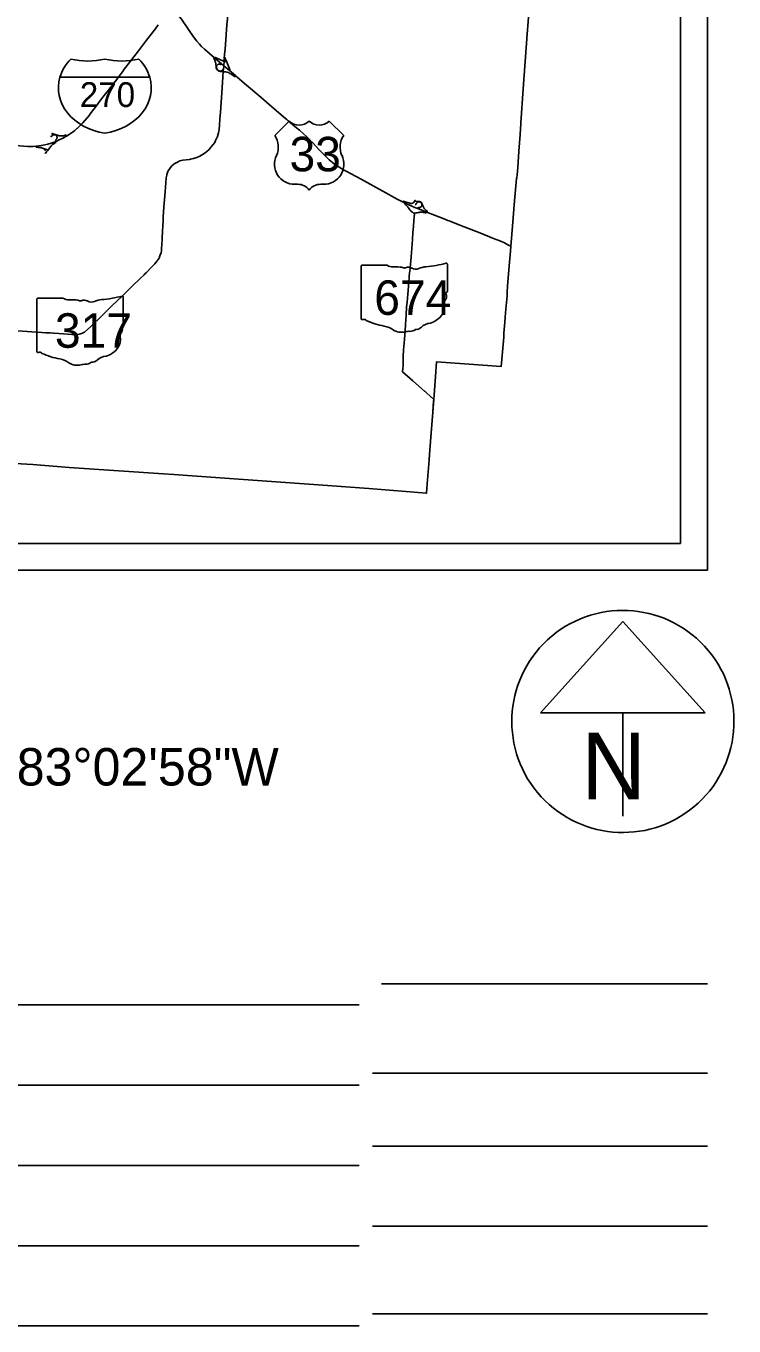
# Model space of a CAD drawing. Extents: x -7.1 to 34, y 0 to 22.
# Drawn here: x 6.456 to 9.099, y 11.177 to 16.034 of the extents above; entities that cross this region are included whole.
import ezdxf

# ---------------------------------------------------------------- set-up
doc = ezdxf.new("R2010")
doc.units = 0
for name, color, linetype in [('GM_X_County', 7, 'Continuous'), ('GM_X_Interchange_Ramps', 7, 'Continuous'), ('GM_X_Interstate_Route', 7, 'Continuous'), ('GM_X_Interstate_Shield', 7, 'Continuous'), ('GM_X_State_Route', 7, 'Continuous'), ('GM_X_State_Shield', 7, 'Continuous'), ('GM_X_US_Route', 7, 'Continuous'), ('GM_X_US_Shield', 7, 'Continuous'), ('SH_Data', 7, 'Continuous'), ('SH_Text', 7, 'Continuous')]:
    doc.layers.add(name, color=color, linetype=linetype)

msp = doc.modelspace()

# ---------------------------------------------------------------- linework, layer by layer
at = {"layer": 'GM_X_County'}
msp.add_lwpolyline([(8.3452, 16.241), (8.3276, 16.0031), (8.3124, 15.7982), (8.3039, 15.672), (8.304, 15.6696), (8.3007, 15.6277), (8.2962, 15.5663), (8.2918, 15.5054), (8.2895, 15.4769), (8.2885, 15.4678), (8.2869, 15.4635), (8.2799, 15.3798), (8.2697, 15.255), (8.2659, 15.2104), (8.2648, 15.1927), (8.2633, 15.1786), (8.262, 15.1645), (8.2613, 15.1511), (8.2536, 15.0634), (8.2526, 15.0382), (8.2529, 15.0363), (8.2526, 15.0324), (8.2521, 15.0258), (8.2478, 14.9762), (8.2466, 14.9608), (8.2454, 14.9453), (8.2439, 14.9276), (8.2404, 14.8854), (8.2396, 14.8706), (8.2296, 14.7611), (8.111, 14.7704), (7.9888, 14.7793), (7.9845, 14.7241), (7.9794, 14.6555), (7.9781, 14.638), (7.9638, 14.4503), (7.9612, 14.4126), (7.9539, 14.3229), (7.9514, 14.288), (7.7354, 14.3054), (7.582, 14.317), (7.338, 14.3346), (7.2153, 14.3436), (7.0933, 14.3519), (7.0075, 14.3585), (6.9696, 14.3609), (6.617, 14.3844), (6.4816, 14.3958), (6.2397, 14.409)], dxfattribs=at)
at = {"layer": 'GM_X_Interchange_Ramps'}
for points in [[(7.1594, 15.9152), (7.1567, 15.9122), (7.1586, 15.9096), (7.1597, 15.9078), (7.1607, 15.9059), (7.1614, 15.9043), (7.1621, 15.9026), (7.1628, 15.9008), (7.1633, 15.8989), (7.1638, 15.8965), (7.1641, 15.8941), (7.1658, 15.8772), (7.1664, 15.875), (7.1671, 15.8733), (7.1679, 15.8718), (7.1691, 15.8702), (7.1706, 15.8686), (7.1718, 15.8675), (7.1733, 15.8665), (7.1748, 15.8657), (7.1761, 15.8651), (7.1779, 15.8646), (7.1795, 15.8643), (7.1817, 15.864), (7.1905, 15.8631), (7.1924, 15.863)], [(7.1952, 15.9017), (7.1938, 15.9018), (7.1687, 15.9134), (7.1636, 15.9163), (7.1612, 15.9136)], [(7.193, 15.8705), (7.1905, 15.8707), (7.1896, 15.8695), (7.1884, 15.8683), (7.1872, 15.8673), (7.1859, 15.8666), (7.1847, 15.8661), (7.1835, 15.8657), (7.1818, 15.8654), (7.1802, 15.8654), (7.1786, 15.8656), (7.1769, 15.8661), (7.1742, 15.8675), (7.1723, 15.8688), (7.1707, 15.8703), (7.1693, 15.8721), (7.1684, 15.8737), (7.1678, 15.8751), (7.1672, 15.8771), (7.1669, 15.8791), (7.1669, 15.8813), (7.1673, 15.8835), (7.1679, 15.8849), (7.1685, 15.8862), (7.1694, 15.8873), (7.1708, 15.8887), (7.1722, 15.8896), (7.1738, 15.8904), (7.1754, 15.8909), (7.177, 15.8911), (7.1788, 15.891), (7.1802, 15.8908), (7.1814, 15.8904), (7.183, 15.8897), (7.1858, 15.8925)], [(7.2053, 15.8984), (7.2047, 15.8982), (7.2039, 15.8991), (7.2028, 15.9), (7.2017, 15.9006), (7.2004, 15.9012), (7.1991, 15.9015), (7.1983, 15.9015), (7.1974, 15.9016), (7.1952, 15.9017)], [(7.2152, 15.8674), (7.2175, 15.8699), (7.2155, 15.8736), (7.2053, 15.8984), (7.1995, 15.9125), (7.1984, 15.9154), (7.1961, 15.9155)], [(7.1924, 15.863), (7.194, 15.8629), (7.1986, 15.8625), (7.2001, 15.8624), (7.2019, 15.8621), (7.2068, 15.861), (7.2107, 15.8598), (7.2142, 15.8582), (7.2173, 15.8566), (7.2204, 15.8547), (7.2364, 15.8441), (7.239, 15.847)], [(6.5266, 15.5596), (6.5297, 15.5585), (6.5311, 15.5607), (6.5328, 15.5633), (6.536, 15.5674), (6.5398, 15.5718), (6.5471, 15.5826), (6.5482, 15.5838), (6.5496, 15.5853), (6.551, 15.5867), (6.5524, 15.588), (6.554, 15.5894), (6.5554, 15.5906), (6.5568, 15.5916), (6.5585, 15.5929), (6.5618, 15.595), (6.5631, 15.5958), (6.5648, 15.5968), (6.5667, 15.5977), (6.5653, 15.6013)], [(6.5479, 15.6216), (6.551, 15.6205), (6.5524, 15.6224), (6.5537, 15.624), (6.5549, 15.625), (6.5561, 15.6257), (6.5582, 15.6268), (6.5602, 15.6272), (6.562, 15.6273), (6.5643, 15.627), (6.5657, 15.6265), (6.5679, 15.6254), (6.5692, 15.6241), (6.5702, 15.6228), (6.5709, 15.6216), (6.5714, 15.6202), (6.5718, 15.6184), (6.5719, 15.6165), (6.5716, 15.6144), (6.571, 15.6126), (6.5703, 15.6111), (6.5689, 15.6095), (6.5677, 15.6084), (6.5664, 15.6075), (6.5683, 15.6025)], [(6.5515, 15.6315), (6.5531, 15.631), (6.5602, 15.6287), (6.5602, 15.6272)], [(6.607, 15.6222), (6.6042, 15.6264), (6.6024, 15.6256), (6.6006, 15.6248), (6.5986, 15.6241), (6.5967, 15.6236), (6.5947, 15.6232), (6.5931, 15.6229), (6.5909, 15.6227), (6.5887, 15.6226), (6.5864, 15.6226), (6.584, 15.6228), (6.5817, 15.6232), (6.5794, 15.6237), (6.5766, 15.6246), (6.5642, 15.6286), (6.5534, 15.6321), (6.5519, 15.6326)], [(6.4939, 15.5841), (6.4942, 15.5806), (6.5013, 15.5802), (6.503, 15.5802), (6.5049, 15.58), (6.5066, 15.5798), (6.5081, 15.5795), (6.5098, 15.5792), (6.5112, 15.5789), (6.5129, 15.5785), (6.5152, 15.5778), (6.5172, 15.5772), (6.5191, 15.5765), (6.5217, 15.5753), (6.5226, 15.5748), (6.5235, 15.5742), (6.5242, 15.5736), (6.5247, 15.573), (6.5253, 15.5722), (6.5258, 15.5712), (6.5263, 15.5702), (6.5297, 15.5688)], [(6.5217, 15.5753), (6.5218, 15.5756), (6.5281, 15.5735), (6.5309, 15.5721)], [(6.5309, 15.5721), (6.5326, 15.5716), (6.5343, 15.5712), (6.5355, 15.5711), (6.5368, 15.5713), (6.5381, 15.5717), (6.5393, 15.5724), (6.5398, 15.5718)], [(7.91, 15.3812), (7.9072, 15.3814), (7.9062, 15.3787), (7.9055, 15.3772), (7.9046, 15.3759), (7.9036, 15.3747), (7.9024, 15.3735), (7.9012, 15.3727), (7.8997, 15.3719), (7.898, 15.3713), (7.8965, 15.3709), (7.8952, 15.3708), (7.8937, 15.3707), (7.892, 15.3709), (7.8865, 15.3723), (7.8715, 15.377), (7.8655, 15.3792), (7.8637, 15.3754)], [(7.8722, 15.3713), (7.8707, 15.368), (7.872, 15.367), (7.8739, 15.3654), (7.8757, 15.3637), (7.8779, 15.3616), (7.88, 15.3592), (7.8819, 15.357), (7.8836, 15.3546), (7.8889, 15.347), (7.89, 15.3454), (7.8914, 15.3437), (7.8929, 15.3421), (7.8947, 15.3405), (7.8968, 15.339), (7.8986, 15.3376), (7.9003, 15.3365), (7.9018, 15.3357), (7.9032, 15.3349), (7.9063, 15.3342)], [(7.9089, 15.3664), (7.9109, 15.3662), (7.9117, 15.3683), (7.9124, 15.3696), (7.9134, 15.3714), (7.9146, 15.3729), (7.9157, 15.3741), (7.9174, 15.3753), (7.9193, 15.3762), (7.9214, 15.3768), (7.9236, 15.3769), (7.9256, 15.3766), (7.9273, 15.376), (7.9289, 15.3752), (7.9301, 15.3743), (7.9314, 15.3731), (7.9323, 15.3718), (7.933, 15.3705), (7.9337, 15.3688), (7.934, 15.367), (7.934, 15.3653), (7.9338, 15.3636), (7.9334, 15.362), (7.9327, 15.3606), (7.9318, 15.3593), (7.9308, 15.358), (7.9294, 15.3569), (7.9278, 15.356), (7.9262, 15.3553), (7.9246, 15.355), (7.9221, 15.3549), (7.9209, 15.3552), (7.9192, 15.3513)], [(7.9525, 15.3381), (7.9542, 15.3419), (7.9521, 15.3432), (7.9503, 15.3444), (7.9487, 15.3456), (7.9473, 15.3469), (7.9457, 15.3484), (7.9442, 15.3502), (7.9431, 15.3515), (7.9421, 15.353), (7.9411, 15.3545), (7.9401, 15.3563), (7.9394, 15.3579), (7.9388, 15.3593), (7.9343, 15.3704), (7.9334, 15.3722), (7.9322, 15.3738), (7.931, 15.375), (7.9295, 15.3761), (7.9282, 15.3768), (7.9269, 15.3774), (7.9251, 15.3778), (7.9226, 15.3784), (7.911, 15.379), (7.9098, 15.3791)]]:
    msp.add_lwpolyline(points, dxfattribs=at)
at = {"layer": 'GM_X_Interstate_Route'}
for points in [[(6.9491, 16.0374), (6.938, 16.0223), (6.9058, 15.9807), (6.88, 15.9462), (6.8459, 15.9025), (6.8229, 15.8718)], [(6.8157, 15.8622), (6.8112, 15.8562), (6.7971, 15.8373), (6.7622, 15.7924), (6.7383, 15.7616), (6.7143, 15.7292), (6.7102, 15.7237), (6.7093, 15.7225)], [(6.8229, 15.8718), (6.8158, 15.8623), (6.8157, 15.8622)], [(6.6947, 15.7033), (6.6928, 15.7008), (6.668, 15.6718), (6.6546, 15.6581), (6.6466, 15.6505), (6.6461, 15.6501)], [(6.7093, 15.7225), (6.6958, 15.7048), (6.6947, 15.7033)], [(6.6461, 15.6501), (6.6382, 15.6432), (6.6288, 15.6362), (6.607, 15.6222), (6.5933, 15.6141), (6.5776, 15.6067), (6.5683, 15.6025), (6.5653, 15.6013), (6.5622, 15.6), (6.5612, 15.5996)], [(6.5376, 15.5925), (6.526, 15.5895), (6.513, 15.5868), (6.4939, 15.5841), (6.4831, 15.5835), (6.4614, 15.5831), (6.4322, 15.5853), (6.3196, 15.593), (6.3129, 15.5934), (6.3105, 15.5936)], [(6.5612, 15.5996), (6.5608, 15.5994), (6.5499, 15.5956), (6.5376, 15.5925)]]:
    msp.add_lwpolyline(points, dxfattribs=at)
at = {"layer": 'GM_X_Interstate_Shield'}
msp.add_line((6.918, 15.8422), (6.5824, 15.8422), dxfattribs=at)
msp.add_line((6.918, 15.8422), (6.5824, 15.8422), dxfattribs=at)
for centre, start_param, end_param in [((6.7936, 15.8026), 2.47259, 2.911027), ((6.6868, 16.0762), 4.415841, 5.008937), ((6.8136, 16.0762), 4.415841, 5.008937), ((6.7069, 15.8026), 0.230566, 0.669003), ((6.7936, 15.8026), 2.911027, 4.511031), ((6.7069, 15.8026), 4.913747, 6.513751)]:
    msp.add_ellipse(centre, major_axis=(0.2169, 0), ratio=0.8, start_param=start_param, end_param=end_param, dxfattribs=at)
at = {"layer": 'GM_X_State_Route'}
for points in [[(7.1972, 15.928), (7.1989, 15.9466), (7.2059, 16.0375), (7.2079, 16.0605), (7.2092, 16.0799)], [(7.1926, 15.8655), (7.193, 15.8705), (7.1941, 15.8853)], [(7.1941, 15.8853), (7.1952, 15.9017), (7.1961, 15.9155), (7.1967, 15.923)], [(7.1967, 15.923), (7.1972, 15.928)], [(6.9819, 15.479), (6.9839, 15.4857), (6.9872, 15.4927), (6.9926, 15.5013), (6.9995, 15.5098), (7.0091, 15.5181), (7.0141, 15.5214), (7.0212, 15.5254), (7.0303, 15.5293), (7.0354, 15.531), (7.0409, 15.5322), (7.0658, 15.5351), (7.0745, 15.5367), (7.0812, 15.5382), (7.0936, 15.5423), (7.1044, 15.5471), (7.1148, 15.5529), (7.1245, 15.5596), (7.1311, 15.5646), (7.1397, 15.5727), (7.1466, 15.5807), (7.1543, 15.5903), (7.1606, 15.5989), (7.164, 15.6055), (7.1676, 15.6132), (7.1708, 15.621), (7.1746, 15.6347), (7.176, 15.6411), (7.1766, 15.6476), (7.1781, 15.6622), (7.1801, 15.6872), (7.1816, 15.7098), (7.1849, 15.7496), (7.1873, 15.7823), (7.1911, 15.844)], [(7.1911, 15.844), (7.1924, 15.863), (7.1926, 15.8655)], [(6.9686, 15.32), (6.9711, 15.3569), (6.975, 15.4138), (6.979, 15.4657), (6.9812, 15.4766), (6.9819, 15.479)], [(6.9668, 15.2835), (6.9671, 15.2885), (6.9676, 15.3045), (6.9686, 15.32)], [(7.8987, 15.2375), (7.9007, 15.2617), (7.9025, 15.2842), (7.9044, 15.3087), (7.9051, 15.3176)], [(7.9051, 15.3176), (7.9063, 15.3342)], [(7.9063, 15.3342), (7.9112, 15.335), (7.9164, 15.3359), (7.921, 15.3368), (7.9237, 15.3371), (7.926, 15.3375), (7.9291, 15.3376), (7.9327, 15.3377), (7.9364, 15.3375), (7.9396, 15.3373), (7.9433, 15.3367), (7.9465, 15.3361), (7.9492, 15.3361), (7.9548, 15.3371)], [(6.9052, 15.113), (6.9231, 15.1311), (6.9367, 15.1451), (6.9461, 15.156), (6.9525, 15.1664), (6.9558, 15.1747), (6.96, 15.1868), (6.9612, 15.192), (6.9624, 15.2014), (6.9646, 15.2356), (6.966, 15.2715), (6.9667, 15.2824), (6.9668, 15.2835)], [(7.8915, 15.1465), (7.8924, 15.1539), (7.8937, 15.1726), (7.8947, 15.1846), (7.896, 15.2046), (7.8984, 15.2345), (7.8987, 15.2375)], [(6.8965, 15.1043), (6.9001, 15.1079), (6.9052, 15.113)], [(7.8638, 14.7871), (7.8637, 14.7891), (7.8637, 14.7977), (7.8638, 14.8018), (7.864, 14.805), (7.8642, 14.8088), (7.8648, 14.8152), (7.8657, 14.824), (7.8676, 14.8482), (7.8686, 14.8632), (7.871, 14.8943), (7.8725, 14.9186), (7.8748, 14.9534), (7.8771, 14.9839), (7.8787, 15.0019), (7.881, 15.0312), (7.8822, 15.045), (7.8838, 15.0626), (7.8866, 15.093), (7.887, 15.0988), (7.889, 15.1198)], [(7.889, 15.1198), (7.8897, 15.1271), (7.8915, 15.1465)], [(6.6297, 14.8808), (6.6427, 14.8804), (6.6488, 14.881), (6.6545, 14.882), (6.6591, 14.8832), (6.6637, 14.8847), (6.6692, 14.8871), (6.6745, 14.8899), (6.6984, 14.9105), (6.7384, 14.9501), (6.7769, 14.9884), (6.8145, 15.0246), (6.8307, 15.0398), (6.8515, 15.0601), (6.8838, 15.0918), (6.8965, 15.1043)], [(6.3981, 14.8966), (6.4254, 14.895), (6.4778, 14.8913), (6.478, 14.8913)], [(6.478, 14.8913), (6.5149, 14.8884), (6.5289, 14.8874), (6.5315, 14.8873)], [(6.5315, 14.8873), (6.5458, 14.8867), (6.5586, 14.8857), (6.5599, 14.8856)], [(6.5599, 14.8856), (6.5963, 14.8832), (6.6274, 14.8808), (6.6297, 14.8808)], [(7.8633, 14.7554), (7.8633, 14.7556), (7.8637, 14.7623), (7.864, 14.7692), (7.8641, 14.7748), (7.8638, 14.7871)], [(7.8619, 14.7409), (7.8619, 14.7409), (7.8633, 14.7554)], [(7.9781, 14.638), (7.9632, 14.6524), (7.9528, 14.6619), (7.9445, 14.6689), (7.9439, 14.6695), (7.9002, 14.7073), (7.8619, 14.7409)], [(7.9746, 14.5911), (7.9777, 14.6331)], [(7.9777, 14.6331), (7.9781, 14.638)], [(7.9613, 14.4139), (7.9638, 14.4503), (7.9746, 14.5911)]]:
    msp.add_lwpolyline(points, dxfattribs=at)
at = {"layer": 'GM_X_State_Shield'}
for p, q in [((7.7071, 15.1361), (7.7071, 14.9405)), ((7.8046, 15.1395), (7.7103, 15.1395)), ((8.0292, 15.042), (8.0292, 15.1443)), ((6.4964, 15.0132), (6.4964, 14.8176)), ((6.5939, 15.0165), (6.4996, 15.0165)), ((6.8185, 14.9191), (6.8185, 15.0214)), ((8.0292, 15.0421), (8.0292, 15.042)), ((6.8185, 14.9191), (6.8185, 14.9191))]:
    msp.add_line(p, q, dxfattribs=at)
for centre, major_axis, start_param, end_param in [((7.7108, 15.1365), (0.00373, 0), 1.712693, 3.28349), ((7.8271, 15.1622), (0.0362, 0), 4.042523, 4.731795), ((7.8391, 15.0297), (0.1299, 0), 1.404758, 1.657858), ((7.8686, 15.1376), (0.0104, 0), 3.836095, 5.185415), ((7.8839, 15.115), (0.0217, 0), 0.950623, 2.079405), ((7.9119, 15.146), (0.0261, 0), 4.081561, 5.145723), ((7.958, 15.0798), (0.0687, 0), 1.699011, 2.107814), ((7.9145, 15.4061), (0.3416, 0), 4.814394, 5.042369), ((8.0256, 15.1448), (0.00359, 0), 6.141152, 7.989035), ((6.5001, 15.0136), (0.00373, 0), 1.712693, 3.28349), ((6.6164, 15.0392), (0.0362, 0), 4.042523, 4.731795), ((6.6284, 14.9067), (0.1299, 0), 1.404758, 1.657858), ((6.6579, 15.0146), (0.0104, 0), 3.836095, 5.185415), ((6.6732, 14.992), (0.0217, 0), 0.950623, 2.079405), ((6.7473, 14.9568), (0.0687, 0), 1.699011, 2.107814), ((6.7038, 15.2832), (0.3416, 0), 4.814394, 5.042369), ((6.8149, 15.0218), (0.00359, 0), 6.141152, 7.989035), ((8.042, 14.9992), (0.0242, 0), 2.387724, 3.262537), ((8.0284, 15.0345), (0.00555, 0), 1.883978, 3.671073), ((7.9931, 15.0216), (0.0333, 0), 5.934695, 6.695948), ((8.0254, 15.0416), (0.00384, 0), 5.05454, 6.418171), ((6.7012, 15.023), (0.0261, 0), 4.081561, 5.145723), ((7.9336, 14.9862), (0.0854, 0), 5.101752, 6.440018), ((6.8177, 14.9115), (0.00555, 0), 1.883978, 3.671073), ((6.8147, 14.9187), (0.00384, 0), 5.05454, 6.418171), ((7.7108, 14.9401), (0.00376, 0), 3.00124, 4.508301), ((7.7114, 14.9601), (0.0287, 0), 4.665946, 4.897461), ((7.7173, 14.9293), (0.0104, 0), 0.519207, 1.627899), ((7.8481, 15.105), (0.2467, 0), 4.195997, 4.488961), ((7.7745, 14.8527), (0.0772, 0), 0.823519, 1.323587), ((7.9696, 14.8856), (0.0468, 0), 1.647645, 2.488434), ((6.7229, 14.8632), (0.0854, 0), 5.101752, 6.440018), ((6.8314, 14.8762), (0.0242, 0), 2.387724, 3.262537), ((6.7824, 14.8986), (0.0333, 0), 5.934695, 6.695948), ((7.858, 14.9283), (0.049, 0), 4.026481, 4.996735), ((7.8863, 14.8607), (0.0402, 0), 1.495662, 1.94098), ((7.8899, 14.9136), (0.0261, 0), 4.691044, 5.507374), ((7.9135, 14.8947), (0.00735, 0), 1.147584, 2.315152), ((7.9103, 14.9216), (0.0276, 0), 4.937069, 5.64225), ((6.5001, 14.8171), (0.00376, 0), 3.00124, 4.508301), ((6.5007, 14.8372), (0.0287, 0), 4.665946, 4.897461), ((6.5066, 14.8063), (0.0104, 0), 0.519207, 1.627899), ((6.6374, 14.982), (0.2467, 0), 4.195997, 4.488961), ((6.5638, 14.7297), (0.0772, 0), 0.823519, 1.323587), ((6.6473, 14.8053), (0.049, 0), 4.026481, 4.996735), ((6.6756, 14.7377), (0.0402, 0), 1.495662, 1.94098), ((6.6792, 14.7907), (0.0261, 0), 4.691044, 5.507374), ((6.7028, 14.7717), (0.00735, 0), 1.147584, 2.315152), ((6.6996, 14.7986), (0.0276, 0), 4.937069, 5.64225), ((6.7589, 14.7627), (0.0468, 0), 1.647645, 2.488434)]:
    msp.add_ellipse(centre, major_axis=major_axis, ratio=0.8, start_param=start_param, end_param=end_param, dxfattribs=at)
at = {"layer": 'GM_X_US_Route'}
for points in [[(6.9922, 16.1014), (6.9961, 16.0989), (6.998, 16.0975), (7.0035, 16.093), (7.0112, 16.0866), (7.0176, 16.0805), (7.0234, 16.0744), (7.0294, 16.0679), (7.036, 16.0592), (7.0412, 16.0522), (7.055, 16.0319), (7.0705, 16.009), (7.0852, 15.9878), (7.0942, 15.9766), (7.1036, 15.9656), (7.1117, 15.957), (7.122, 15.9472), (7.1594, 15.9152), (7.1612, 15.9136), (7.1858, 15.8925), (7.1941, 15.8853)], [(7.1941, 15.8853), (7.2152, 15.8674), (7.2215, 15.8619)], [(7.2215, 15.8619), (7.239, 15.847), (7.2427, 15.8438)], [(7.2427, 15.8438), (7.2718, 15.8191), (7.2938, 15.8001), (7.3099, 15.7864)], [(7.3099, 15.7864), (7.3338, 15.7659), (7.382, 15.7247), (7.4246, 15.6881), (7.4294, 15.6838), (7.4345, 15.6794), (7.4602, 15.6579), (7.4767, 15.6438), (7.5041, 15.6194), (7.5161, 15.6074), (7.5268, 15.5967), (7.551, 15.5712), (7.5715, 15.5494), (7.5881, 15.5334), (7.6, 15.5236), (7.6094, 15.5165), (7.6199, 15.5093), (7.6323, 15.5017), (7.7068, 15.461), (7.7858, 15.4176), (7.7882, 15.4163)], [(7.7882, 15.4163), (7.8417, 15.387), (7.8637, 15.3754), (7.8722, 15.3713), (7.8849, 15.3654), (7.9082, 15.3557)], [(7.9082, 15.3557), (7.9119, 15.3542)], [(7.9119, 15.3542), (7.9192, 15.3513), (7.9525, 15.3381), (7.9548, 15.3371)], [(7.9548, 15.3371), (7.9815, 15.3268), (8.0136, 15.3141), (8.0307, 15.3074), (8.0308, 15.3074)], [(8.0308, 15.3074), (8.0354, 15.3056)], [(8.0354, 15.3056), (8.0421, 15.303), (8.076, 15.2894), (8.1503, 15.2603), (8.201, 15.2402), (8.2148, 15.2348), (8.2317, 15.2282), (8.2423, 15.2233), (8.258, 15.2151), (8.2659, 15.2104)]]:
    msp.add_lwpolyline(points, dxfattribs=at)
at = {"layer": 'GM_X_US_Shield'}
for p, q in [((7.4381, 15.6785), (7.3844, 15.6248)), ((7.6421, 15.6248), (7.5884, 15.6785)), ((7.4595, 15.4423), (7.4703, 15.4423)), ((7.5562, 15.4423), (7.5669, 15.4423))]:
    msp.add_line(p, q, dxfattribs=at)
for centre, radius, start, end in [((7.4756, 15.7168), 0.0537, 225.573, 314.427), ((7.5508, 15.7168), 0.0537, 225.573, 314.427), ((7.3228, 15.5817), 0.0752, 334.5471, 35.0009), ((7.7036, 15.5817), 0.0752, 144.9991, 205.4529), ((7.4587, 15.5174), 0.0752, 154.8319, 270.6383), ((7.5678, 15.5174), 0.0752, 269.3617, 25.1681), ((7.4703, 15.3886), 0.0537, 36.8699, 90), ((7.5562, 15.3886), 0.0537, 90, 143.1301)]:
    msp.add_arc(centre, radius, start, end, dxfattribs=at)
at = {"layer": 'SH_Data'}
for p, q in [((9, 21), (9, 14)), ((8.9, 20.9), (8.9, 14.1)), ((2.1, 14.1), (8.9, 14.1)), ((2, 14), (9, 14)), ((8.6845, 13.8091), (8.3769, 13.4678)), ((8.9921, 13.4678), (8.6845, 13.8091)), ((8.3769, 13.4678), (8.9921, 13.4678)), ((8.6845, 13.4678), (8.6845, 13.0811)), ((8.6845, 13.4353), (8.6845, 13.4353)), ((8.6845, 13.4353), (8.6845, 13.4353)), ((7.7827, 12.4553), (9, 12.4553)), ((7.7, 12.3767), (4.4937, 12.3767)), ((9, 12.1207), (7.75, 12.1207)), ((7.7, 12.0767), (3.9895, 12.0767)), ((9, 11.8491), (7.75, 11.8491)), ((7.7, 11.7767), (3.6192, 11.7767)), ((9, 11.5491), (7.75, 11.5491)), ((7.7, 11.4767), (3.3288, 11.4767)), ((9, 11.2223), (7.75, 11.2223)), ((7.7, 11.1767), (4.7452, 11.1767))]:
    msp.add_line(p, q, dxfattribs=at)
msp.add_arc((8.6845, 13.4353), 0.4148, 129.7798, 129.7633, dxfattribs=at)

# ---------------------------------------------------------------- texts
at = {"layer": 'GM_X_Interstate_Shield'}
msp.add_text('270', height=0.09255, dxfattribs=at).set_placement((6.6568, 15.7309))
at = {"layer": 'GM_X_State_Shield'}
for s, p in [('674', (7.7563, 14.9543)), ('317', (6.5639, 14.8314))]:
    msp.add_text(s, height=0.12885, dxfattribs=at).set_placement(p)
at = {"layer": 'GM_X_US_Shield'}
msp.add_text('33', height=0.12885, dxfattribs=at).set_placement((7.4399, 15.4906))
at = {"layer": 'SH_Data'}
msp.add_text('N', height=0.25, dxfattribs=at).set_placement((8.5292, 13.144))
at = {"layer": 'SH_Text'}
msp.add_text('LATITUDE:  40°17\'52"N  LONGITUDE:  83°02\'58"W  ', height=0.14, dxfattribs=at).set_placement((3.071, 13.1959))

doc.saveas('drawing.dxf')
